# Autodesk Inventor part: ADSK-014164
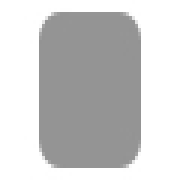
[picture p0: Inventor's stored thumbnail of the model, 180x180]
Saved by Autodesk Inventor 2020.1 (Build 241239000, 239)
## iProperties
Created: 2019-01
Part Number: ADSK-014164
Material: Stahl, weich
Document SubType Name: Modeling
Designer: lutzd
Language: de-DE
Size Designation: 5 x 60 x 40
Categories: <MemberInstance><Categories><Category DisplayName="Sonstige Bauteile" InternalName="5aa15e00-363f-49f2-933f-16f664388e3f" Mnemonic="OTHER"><Category DisplayName
Mass: 93.3577 g
Surface Area: 57.1416 cm^2
Volume: 11.8927 cm^3
Density: 7.85 g/cm^3
Appearance: Halbpoliert
IsCustomPart: 1
Title: end cap
Author: lutzd
Revision Number: -
Dimensions: 40x60x5 mm
Mass: 0,093 kg
DocNumber: ADSK-014164
Folder: 01 - Themengebiete\Simplification\01 - Packaging machine\
VDS_Category: 3D Komponenten
VDS_NumSchm: Autodesk
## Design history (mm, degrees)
sketch "Sketch1"
  geometry: L1 (0, 20.175)-(0, -21.446); L2 (-20.203, 0)-(20.169, 0); L3 (-20, 30)-(20, 30); L4 (20, 30)-(20, -30); L5 (20, -30)-(-20, -30); L6 (-20, -30)-(-20, 30); 1 further point
  constraints: 12 end point, 2 horizontal, 2 parallel, 2 point on line, 1 perpendicular, 1 vertical
  dimensions: "d0" = 60 distance between parallel lines of L5 L3 (= height); "d1" = 30 distance between parallel lines of L2 L3 (= 0.5 x height); "d2" = 40 distance between parallel lines of L6 L4 (= width); "d3" = 20 distance between parallel lines of L6 L1 (= 0.5 x width)
extrude "Extrusion1" new body sketch "Sketch1" distance "d4" = 5 (= thickness); taper "d5" = 0 deg
fillet "Fillet1" dims "d6" = 5 (= fillet), "d7" = 0, "fillet" = 5 [user parameter; used in 1 equation term]
chamfer "Chamfer1" distance "d8" = 0 (computed from chamfer); stored, may be unused: second distance "d9" = 2, angle "d10" = 45 deg; dims "d11" = 0, "chamfer" = 0 [user parameter; used in 1 equation term]
body "Solid1"
other parameters: "thickness" = 5 [user parameter; used in 1 equation term], "width" = 40 [user parameter; used in 2 equation terms], "height" = 60 [user parameter; used in 2 equation terms]
